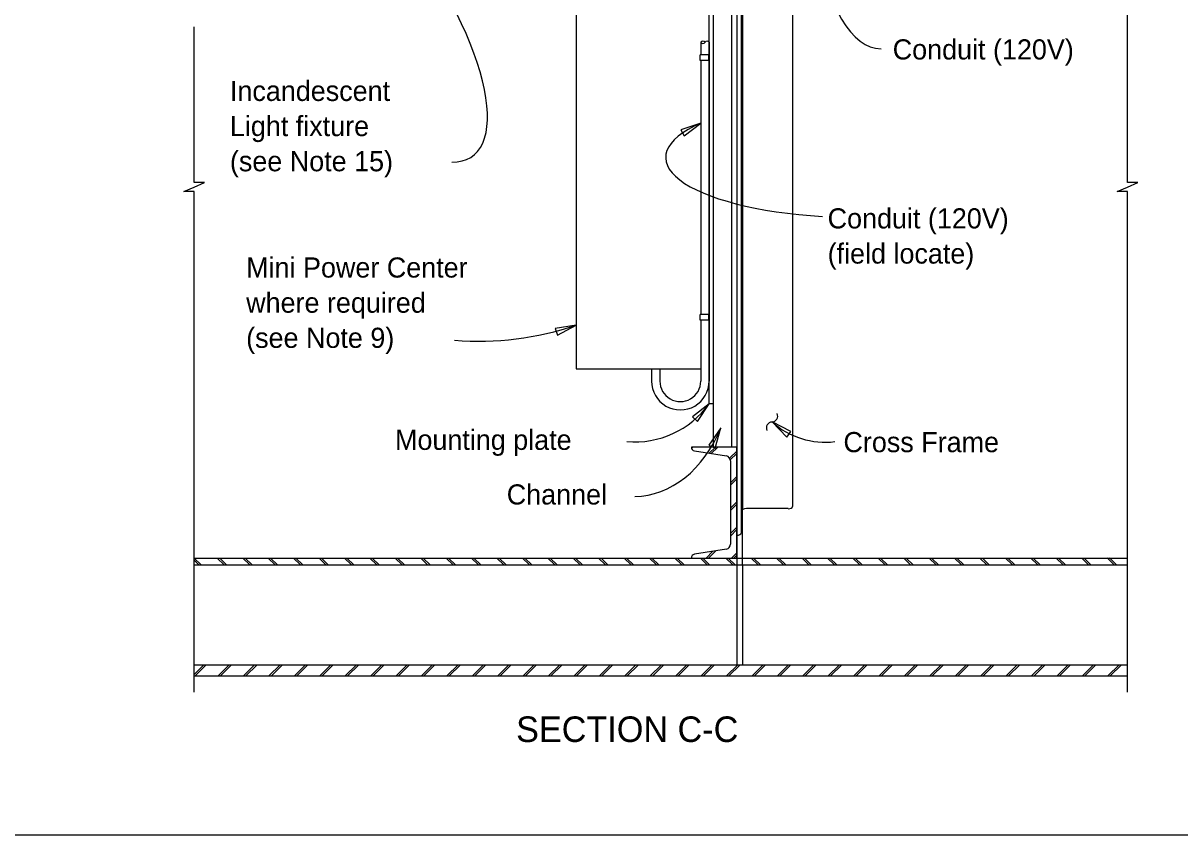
# Model space of a CAD drawing. Extents: x 112544 to 112597.1, y 111084 to 111107.1.
# Drawn here: x 112556.46 to 112565.15, y 111085.9 to 111092 of the extents above; entities that cross this region are included whole.
import ezdxf

# ---------------------------------------------------------------- set-up
doc = ezdxf.new("R2010")
doc.units = 0
for name, color, linetype in [('ActivePts-ConstElements', 7, 'Continuous'), ('Dimension', 7, 'Continuous'), ('Lighting', 7, 'Continuous'), ('Miscellaneous', 7, 'Continuous'), ('SteelGirder', 7, 'Continuous'), ('SteelGirder_h', 7, 'Continuous'), ('TextStructures', 7, 'Continuous')]:
    doc.layers.add(name, color=color, linetype=linetype)

msp = doc.modelspace()

# ---------------------------------------------------------------- linework, layer by layer
at = {"layer": 'ActivePts-ConstElements'}
msp.add_lwpolyline([(112543.9918, 111085.9039), (112574.7797, 111085.9039), (112574.7797, 111105.3634), (112543.9918, 111105.3634)], close=True, dxfattribs=at)
at = {"layer": 'Dimension'}
for points in [[(112564.7526, 111086.9751), (112564.7526, 111090.7348), (112564.6751, 111090.7348), (112564.7526, 111090.7686), (112564.8301, 111090.8023), (112564.7526, 111090.8023), (112564.7526, 111092.9028)], [(112557.7434, 111086.9751), (112557.7434, 111090.7348), (112557.6659, 111090.7348), (112557.7434, 111090.7686), (112557.8209, 111090.8023), (112557.7434, 111090.8023), (112557.7434, 111091.9729)]]:
    msp.add_lwpolyline(points, dxfattribs=at)
for points in [[(112561.5494, 111091.2497), (112561.3992, 111091.1992), (112561.4242, 111091.1526)], [(112560.6119, 111089.7329), (112560.4556, 111089.7071), (112560.4728, 111089.6571)], [(112561.6119, 111089.1409), (112561.4866, 111089.044), (112561.5255, 111089.0081)], [(112561.6995, 111088.9596), (112561.6088, 111088.8297), (112561.6566, 111088.8071)], [(112562.0844, 111089.005), (112562.1943, 111088.8909), (112562.2257, 111088.9335)]]:
    msp.add_lwpolyline(points, close=True, dxfattribs=at)
for centre, radius, start, end in [((112559.8818, 111091.8564), 2.2455, 265.3641, 288.97308), ((112561.0526, 111089.5451), 0.6901, 265.09847, 324.1488), ((112562.0822, 111089.0493), 0.0447, 272.35831, 24.08553), ((112562.0859, 111088.9599), 0.0447, 92.35831, 204.08553), ((112562.4824, 111089.4498), 0.5969, 228.179, 277.09313)]:
    msp.add_arc(centre, radius, start, end, dxfattribs=at)
for centre, major_axis, ratio, start_param, end_param in [((112558.9681, 111092.2177), (-0.8636, 1.2185), 0.378675, 2.874358, 4.819841), ((112562.8948, 111092.9892), (0.0076, -1.1813), 0.426092, 5.02876, 6.283138), ((112562.7558, 111090.9911), (1.4705, 0), 0.307602, 2.532927, 4.511363), ((112561.0378, 111089.4328), (-0.0147, 0.9882), 0.759061, 3.141594, 4.201813)]:
    msp.add_ellipse(centre, major_axis=major_axis, ratio=ratio, start_param=start_param, end_param=end_param, dxfattribs=at)
at = {"layer": 'Lighting'}
for p, q in [((112561.7785, 111093.254), (112561.7785, 111088.8165)), ((112561.5494, 111091.8565), (112561.5494, 111091.7614)), ((112561.6119, 111091.8565), (112561.6119, 111089.3117)), ((112561.5494, 111091.7197), (112561.5494, 111089.8121)), ((112561.5494, 111089.7704), (112561.5494, 111089.3117)), ((112561.1794, 111089.4034), (112561.1794, 111089.3117)), ((112561.2419, 111089.4034), (112561.2419, 111089.3117)), ((112561.6431, 111089.1409), (112561.6431, 111088.8165))]:
    msp.add_line(p, q, dxfattribs=at)
msp.add_lwpolyline([(112561.6119, 111089.4034), (112561.6119, 111092.1284), (112560.6119, 111092.1284), (112560.6119, 111089.4034), (112561.5494, 111089.4034)], dxfattribs=at)
for centre, radius, start, end in [((112561.565, 111091.8478), 0.0179, 29.00268, 150.99744), ((112561.565, 111091.8652), 0.0179, 209.00301, 330.9971), ((112561.5963, 111091.8478), 0.0179, 29.00279, 150.99732), ((112561.3956, 111089.3117), 0.2162, 180, 0.00803), ((112561.3956, 111089.3117), 0.1537, 180, 0.00803)]:
    msp.add_arc(centre, radius, start, end, dxfattribs=at)
at = {"layer": 'Miscellaneous'}
for p, q in [((112561.4802, 111088.8108), (112561.4859, 111088.8165)), ((112561.6129, 111088.7703), (112561.6591, 111088.8165)), ((112561.628, 111088.7678), (112561.6768, 111088.8165)), ((112561.7654, 111088.7319), (112561.8201, 111088.7866)), ((112561.7708, 111088.7196), (112561.8201, 111088.769)), ((112561.7722, 111088.5478), (112561.8201, 111088.5957)), ((112561.7722, 111088.5301), (112561.8201, 111088.578)), ((112561.7722, 111088.3569), (112561.8201, 111088.4048)), ((112561.7722, 111088.3392), (112561.8201, 111088.3871)), ((112561.7722, 111088.166), (112561.8201, 111088.2139)), ((112561.7722, 111088.1483), (112561.8201, 111088.1962)), ((112557.7971, 111087.9311), (112557.745, 111087.9832)), ((112557.9703, 111087.9311), (112557.9182, 111087.9832)), ((112557.988, 111087.9311), (112557.9359, 111087.9832)), ((112558.1613, 111087.9311), (112558.1091, 111087.9832)), ((112558.1789, 111087.9311), (112558.1268, 111087.9832)), ((112558.3522, 111087.9311), (112558.3, 111087.9832)), ((112558.3699, 111087.9311), (112558.3177, 111087.9832)), ((112558.5431, 111087.9311), (112558.491, 111087.9832)), ((112558.5608, 111087.9311), (112558.5086, 111087.9832)), ((112558.734, 111087.9311), (112558.6819, 111087.9832)), ((112558.7517, 111087.9311), (112558.6996, 111087.9832)), ((112558.9249, 111087.9311), (112558.8728, 111087.9832)), ((112558.9426, 111087.9311), (112558.8905, 111087.9832)), ((112559.1158, 111087.9311), (112559.0637, 111087.9832)), ((112559.1335, 111087.9311), (112559.0814, 111087.9832)), ((112559.3068, 111087.9311), (112559.2546, 111087.9832)), ((112559.3244, 111087.9311), (112559.2723, 111087.9832)), ((112559.4977, 111087.9311), (112559.4456, 111087.9832)), ((112559.5154, 111087.9311), (112559.4632, 111087.9832)), ((112559.6886, 111087.9311), (112559.6365, 111087.9832)), ((112559.7063, 111087.9311), (112559.6542, 111087.9832)), ((112559.8795, 111087.9311), (112559.8274, 111087.9832)), ((112559.8972, 111087.9311), (112559.8451, 111087.9832)), ((112560.0704, 111087.9311), (112560.0183, 111087.9832)), ((112560.0881, 111087.9311), (112560.036, 111087.9832)), ((112560.2614, 111087.9311), (112560.2092, 111087.9832)), ((112560.279, 111087.9311), (112560.2269, 111087.9832)), ((112560.4523, 111087.9311), (112560.4001, 111087.9832)), ((112560.47, 111087.9311), (112560.4178, 111087.9832)), ((112560.6432, 111087.9311), (112560.5911, 111087.9832)), ((112560.6609, 111087.9311), (112560.6087, 111087.9832)), ((112560.8341, 111087.9311), (112560.782, 111087.9832)), ((112560.8518, 111087.9311), (112560.7997, 111087.9832)), ((112561.025, 111087.9311), (112560.9729, 111087.9832)), ((112561.0427, 111087.9311), (112560.9906, 111087.9832)), ((112561.216, 111087.9311), (112561.1638, 111087.9832)), ((112561.2336, 111087.9311), (112561.1815, 111087.9832)), ((112561.4069, 111087.9311), (112561.3547, 111087.9832)), ((112561.4246, 111087.9311), (112561.3724, 111087.9832)), ((112561.5978, 111087.9311), (112561.5457, 111087.9832)), ((112561.6155, 111087.9311), (112561.5633, 111087.9832)), ((112561.5895, 111087.9832), (112561.6402, 111088.0339)), ((112561.6071, 111087.9832), (112561.6613, 111088.0374)), ((112561.7887, 111087.9311), (112561.7366, 111087.9832)), ((112561.8064, 111087.9311), (112561.7543, 111087.9832)), ((112561.7804, 111087.9832), (112561.8201, 111088.023)), ((112561.798, 111087.9832), (112561.8201, 111088.0053)), ((112561.9796, 111087.9311), (112561.9275, 111087.9832)), ((112561.9973, 111087.9311), (112561.9452, 111087.9832)), ((112562.1705, 111087.9311), (112562.1184, 111087.9832)), ((112562.1882, 111087.9311), (112562.1361, 111087.9832)), ((112562.3615, 111087.9311), (112562.3093, 111087.9832)), ((112562.3791, 111087.9311), (112562.327, 111087.9832)), ((112562.5524, 111087.9311), (112562.5003, 111087.9832)), ((112562.5701, 111087.9311), (112562.5179, 111087.9832)), ((112562.7433, 111087.9311), (112562.6912, 111087.9832)), ((112562.761, 111087.9311), (112562.7089, 111087.9832)), ((112562.9342, 111087.9311), (112562.8821, 111087.9832)), ((112562.9519, 111087.9311), (112562.8998, 111087.9832)), ((112563.1251, 111087.9311), (112563.073, 111087.9832)), ((112563.1428, 111087.9311), (112563.0907, 111087.9832)), ((112563.3161, 111087.9311), (112563.2639, 111087.9832)), ((112563.3337, 111087.9311), (112563.2816, 111087.9832)), ((112563.507, 111087.9311), (112563.4549, 111087.9832)), ((112563.5247, 111087.9311), (112563.4725, 111087.9832)), ((112563.6979, 111087.9311), (112563.6458, 111087.9832)), ((112563.7156, 111087.9311), (112563.6635, 111087.9832)), ((112563.8888, 111087.9311), (112563.8367, 111087.9832)), ((112563.9065, 111087.9311), (112563.8544, 111087.9832)), ((112564.0798, 111087.9311), (112564.0276, 111087.9832)), ((112564.0974, 111087.9311), (112564.0453, 111087.9832)), ((112564.2707, 111087.9311), (112564.2185, 111087.9832)), ((112564.2884, 111087.9311), (112564.2362, 111087.9832)), ((112564.4616, 111087.9311), (112564.4095, 111087.9832)), ((112564.4793, 111087.9311), (112564.4271, 111087.9832)), ((112564.6525, 111087.9311), (112564.6004, 111087.9833)), ((112564.6702, 111087.9311), (112564.6181, 111087.9833)), ((112557.7794, 111087.9311), (112557.7434, 111087.9672)), ((112557.7434, 111087.1078), (112557.8167, 111087.1812)), ((112557.7511, 111087.0979), (112557.8344, 111087.1812)), ((112557.9244, 111087.0979), (112558.0076, 111087.1812)), ((112557.942, 111087.0979), (112558.0253, 111087.1812)), ((112558.1153, 111087.0979), (112558.1986, 111087.1812)), ((112558.133, 111087.0979), (112558.2162, 111087.1812)), ((112558.3062, 111087.0979), (112558.3895, 111087.1812)), ((112558.3239, 111087.0979), (112558.4072, 111087.1812)), ((112558.4971, 111087.0979), (112558.5804, 111087.1812)), ((112558.5148, 111087.0979), (112558.5981, 111087.1812)), ((112558.688, 111087.0979), (112558.7713, 111087.1812)), ((112558.7057, 111087.0979), (112558.789, 111087.1812)), ((112558.879, 111087.0979), (112558.9622, 111087.1812)), ((112558.8966, 111087.0979), (112558.9799, 111087.1812)), ((112559.0699, 111087.0979), (112559.1532, 111087.1812)), ((112559.0875, 111087.0979), (112559.1708, 111087.1812)), ((112559.2608, 111087.0979), (112559.3441, 111087.1812)), ((112559.2785, 111087.0979), (112559.3617, 111087.1812)), ((112559.4517, 111087.0979), (112559.535, 111087.1812)), ((112559.4694, 111087.0979), (112559.5527, 111087.1812)), ((112559.6426, 111087.0979), (112559.7259, 111087.1812)), ((112559.6603, 111087.0979), (112559.7436, 111087.1812)), ((112559.8335, 111087.0979), (112559.9168, 111087.1812)), ((112559.8512, 111087.0979), (112559.9345, 111087.1812)), ((112560.0245, 111087.0979), (112560.1077, 111087.1812)), ((112560.0421, 111087.0979), (112560.1254, 111087.1812)), ((112560.2154, 111087.0979), (112560.2987, 111087.1812)), ((112560.2331, 111087.0979), (112560.3163, 111087.1812)), ((112560.4063, 111087.0979), (112560.4896, 111087.1812)), ((112560.424, 111087.0979), (112560.5073, 111087.1812)), ((112560.5972, 111087.0979), (112560.6805, 111087.1812)), ((112560.6149, 111087.0979), (112560.6982, 111087.1812)), ((112560.7881, 111087.0979), (112560.8714, 111087.1812)), ((112560.8058, 111087.0979), (112560.8891, 111087.1812)), ((112560.9791, 111087.0979), (112561.0623, 111087.1812)), ((112560.9967, 111087.0979), (112561.08, 111087.1812)), ((112561.17, 111087.0979), (112561.2533, 111087.1812)), ((112561.1877, 111087.0979), (112561.2709, 111087.1812)), ((112561.3609, 111087.0979), (112561.4442, 111087.1812)), ((112561.3786, 111087.0979), (112561.4619, 111087.1812)), ((112561.5518, 111087.0979), (112561.6351, 111087.1812)), ((112561.5695, 111087.0979), (112561.6528, 111087.1812)), ((112561.7427, 111087.0979), (112561.826, 111087.1812)), ((112561.7604, 111087.0979), (112561.8437, 111087.1812)), ((112561.9337, 111087.0979), (112562.0169, 111087.1812)), ((112561.9513, 111087.0979), (112562.0346, 111087.1812)), ((112562.1246, 111087.0979), (112562.2079, 111087.1812)), ((112562.1423, 111087.0979), (112562.2255, 111087.1812)), ((112562.3155, 111087.0979), (112562.3988, 111087.1812)), ((112562.3332, 111087.0979), (112562.4164, 111087.1812)), ((112562.5064, 111087.0979), (112562.5897, 111087.1812)), ((112562.5241, 111087.0979), (112562.6074, 111087.1812)), ((112562.6973, 111087.0979), (112562.7806, 111087.1812)), ((112562.715, 111087.0979), (112562.7983, 111087.1812)), ((112562.8882, 111087.0979), (112562.9715, 111087.1812)), ((112562.9059, 111087.0979), (112562.9892, 111087.1812)), ((112563.0792, 111087.0979), (112563.1625, 111087.1812)), ((112563.0968, 111087.0979), (112563.1801, 111087.1812)), ((112563.2701, 111087.0979), (112563.3534, 111087.1812)), ((112563.2878, 111087.0979), (112563.371, 111087.1812)), ((112563.461, 111087.0979), (112563.5443, 111087.1812)), ((112563.4787, 111087.0979), (112563.562, 111087.1812)), ((112563.6519, 111087.0979), (112563.7352, 111087.1812)), ((112563.6696, 111087.0979), (112563.7529, 111087.1812)), ((112563.8429, 111087.0979), (112563.9261, 111087.1812)), ((112563.8605, 111087.0979), (112563.9438, 111087.1812)), ((112564.0338, 111087.0979), (112564.1171, 111087.1812)), ((112564.0515, 111087.0979), (112564.1347, 111087.1812)), ((112564.2247, 111087.0979), (112564.308, 111087.1812)), ((112564.2424, 111087.0979), (112564.3257, 111087.1812)), ((112564.4156, 111087.098), (112564.4989, 111087.1812)), ((112564.4333, 111087.098), (112564.5166, 111087.1812)), ((112564.6065, 111087.098), (112564.6898, 111087.1812)), ((112564.6242, 111087.098), (112564.7075, 111087.1812))]:
    msp.add_line(p, q, dxfattribs=at)
at = {"layer": 'SteelGirder'}
for p, q in [((112562.2368, 111093.2407), (112562.2368, 111088.3699)), ((112561.8514, 111093.0412), (112561.8514, 111088.1702)), ((112561.8201, 111092.8686), (112561.8201, 111087.9832)), ((112561.6119, 111091.7614), (112561.5442, 111091.7614)), ((112561.5442, 111091.7197), (112561.5442, 111091.7614)), ((112561.6119, 111091.7197), (112561.5442, 111091.7197)), ((112561.6067, 111091.7614), (112561.6067, 111091.7197)), ((112561.6119, 111089.8121), (112561.5442, 111089.8121)), ((112561.5442, 111089.7704), (112561.5442, 111089.8121)), ((112561.6067, 111089.8121), (112561.6067, 111089.7704)), ((112561.6119, 111089.7704), (112561.5442, 111089.7704)), ((112561.8201, 111088.8165), (112561.4785, 111088.8165)), ((112561.5024, 111088.7883), (112561.7409, 111088.7493)), ((112561.8201, 111087.9832), (112561.8201, 111088.8165)), ((112561.7722, 111088.7124), (112561.7722, 111088.0874)), ((112561.8618, 111087.9832), (112561.8618, 111088.3465)), ((112562.2056, 111088.3538), (112561.8931, 111088.3538)), ((112557.7434, 111087.9832), (112564.7526, 111087.9832)), ((112561.4785, 111087.9832), (112561.8201, 111087.9832)), ((112561.7409, 111088.0504), (112561.5024, 111088.0114)), ((112557.7434, 111087.9311), (112564.7526, 111087.9311)), ((112561.8201, 111087.9311), (112561.8201, 111087.1812)), ((112561.8618, 111087.9311), (112561.8618, 111087.1812)), ((112557.7434, 111087.1812), (112564.7526, 111087.1812)), ((112557.7434, 111087.0979), (112564.7526, 111087.0979))]:
    msp.add_line(p, q, dxfattribs=at)
msp.add_lwpolyline([(112561.6119, 111092.3909), (112561.6431, 111092.3909), (112561.6431, 111089.1409), (112561.6119, 111089.1409)], close=True, dxfattribs=at)
for centre, radius, start, end in [((112561.5071, 111088.8165), 0.0286, 180, 260.5), ((112561.7347, 111088.7124), 0.0375, 360, 80.5), ((112561.7347, 111088.0874), 0.0375, 279.5, 360), ((112561.5071, 111087.9832), 0.0286, 99.5, 180)]:
    msp.add_arc(centre, radius, start, end, dxfattribs=at)
for centre, major_axis, end_param in [((112561.8931, 111088.3322), (-0.0417, 0), 6.283185), ((112562.2056, 111088.3699), (0.0313, 0), 6.283185), ((112561.8201, 111088.1705), (0.0312, 0), 6.270045)]:
    msp.add_ellipse(centre, major_axis=major_axis, ratio=0.5176, start_param=4.712389, end_param=end_param, dxfattribs=at)
at = {"layer": 'SteelGirder_h'}
for p, q in [((112561.8618, 111093.2407), (112561.8618, 111088.3465)), ((112561.8201, 111087.9832), (112561.8201, 111087.9311)), ((112561.8618, 111087.9311), (112561.8618, 111087.9832))]:
    msp.add_line(p, q, dxfattribs=at)

# ---------------------------------------------------------------- texts
at = {"layer": 'Dimension'}
for s, p in [('Incandescent', (112558.0128, 111091.4156)), ('Light fixture', (112558.0128, 111091.1516)), ('(see Note 15)', (112558.0128, 111090.8876)), ('Conduit (120V)', (112562.5016, 111090.4583)), ('(field locate)', (112562.5016, 111090.1943)), ('Mini Power Center', (112558.1348, 111090.0893)), ('where required', (112558.1348, 111089.8253)), ('(see Note 9)', (112558.1348, 111089.5613))]:
    msp.add_text(s, height=0.1512, dxfattribs=at).set_placement(p)
at = {"layer": 'TextStructures'}
for s, height, p in [('Conduit (120V)', 0.1512, (112562.9903, 111091.7273)), ('Mounting plate', 0.1512, (112559.2525, 111088.7952)), ('Cross Frame', 0.1512, (112562.6203, 111088.778)), ('Channel', 0.1512, (112560.0917, 111088.385)), ('SECTION C-C', 0.192, (112560.162, 111086.6013))]:
    msp.add_text(s, height=height, dxfattribs=at).set_placement(p)

doc.saveas('drawing.dxf')
